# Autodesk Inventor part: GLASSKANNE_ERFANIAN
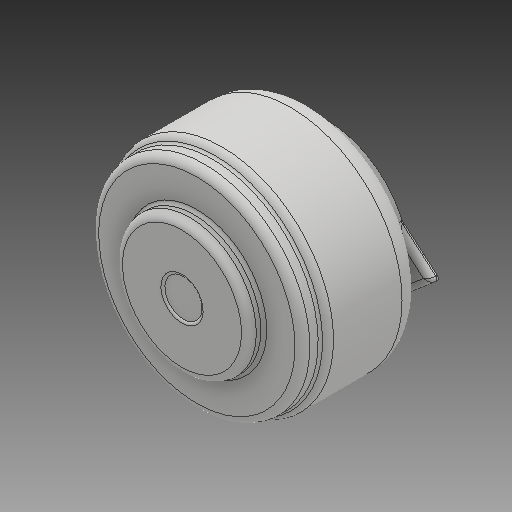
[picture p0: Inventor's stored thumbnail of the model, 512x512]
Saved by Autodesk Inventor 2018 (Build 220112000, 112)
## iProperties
Created: 2019-01
Part Number: GLASSKANNE_ERFANIAN
Material: Generisch
Document SubType Name: Modeling
Designer: zand
Density: 1 g/cm^3
Appearance: Vorgabe
Author: zand
Revision Number: 19LAST_VERSION
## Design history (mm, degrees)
feature "Basis1"
node "Volumenkörper1"
